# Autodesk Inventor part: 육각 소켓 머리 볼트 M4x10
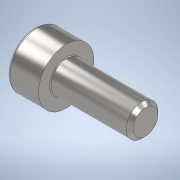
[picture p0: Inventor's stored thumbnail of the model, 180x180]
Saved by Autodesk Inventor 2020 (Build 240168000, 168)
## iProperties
Created: 2024-05
Part Number: 육각 소켓 머리 볼트 M4x10
Material: 강철, 연강
Description: 6각머리 태핑 나사
Document SubType Name: Modeling
Designer: oem
Density: 7.85 g/cm^3
Appearance: 기본값
Author: jhkim
Sending System: Autodesk Inventor 2025
Preprocessor: ST-DEVELOPER v20
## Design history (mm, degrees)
node "육각 소켓 머리 볼트 M4x101"
node "솔리드1"
body "Solid1"
